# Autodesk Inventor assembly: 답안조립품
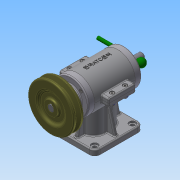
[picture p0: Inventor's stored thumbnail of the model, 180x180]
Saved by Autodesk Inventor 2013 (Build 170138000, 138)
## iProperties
Created: 2015-12
Part Number: 답안조립품
Document SubType Name: Assembly
Designer: Administrator
Author: Administrator
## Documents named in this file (19)
- C:\Users\Administrator\Desktop\351208V1024\답안조립품.iam
- C:\Users\Administrator\Desktop\351208V1024\본체.ipt
- C:\Users\Administrator\Desktop\351208V1024\V-벨트풀리.ipt
- C:\Users\Administrator\Desktop\351208V1024\너트 M4.ipt
- C:\Users\Administrator\Desktop\351208V1024\뒤커버.ipt
- C:\Users\Administrator\Desktop\351208V1024\레바.ipt
- C:\Users\Administrator\Desktop\351208V1024\멈춤나사 M3x8.ipt
- C:\Users\Administrator\Desktop\351208V1024\베어링 6201.ipt
- C:\Users\Administrator\Desktop\351208V1024\베어링 6202.ipt
- C:\Users\Administrator\Desktop\351208V1024\본체커버.ipt
- C:\Users\Administrator\Desktop\351208V1024\볼트 M3x0.5x8.ipt
- C:\Users\Administrator\Desktop\351208V1024\볼트 M4 x 16.ipt
- C:\Users\Administrator\Desktop\351208V1024\스프링.ipt
- C:\Users\Administrator\Desktop\351208V1024\슬라이드.ipt
- C:\Users\Administrator\Desktop\351208V1024\앞커버.ipt
- C:\Users\Administrator\Desktop\351208V1024\오일실 12 22 7.ipt
- C:\Users\Administrator\Desktop\351208V1024\와셔 ST 4-100.ipt
- C:\Users\Administrator\Desktop\351208V1024\키 4 x 4 x 18.ipt
- C:\Users\Administrator\Desktop\351208V1024\편심축.ipt
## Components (13 placed, 4 different names)
1. V-벨트풀리:1 — 플러쉬:1
2. ISO 4032 M4:1
3. ISO 4762 M4 x 16:1
4. ISO 7091 ST 4 - 100 HV:1
5. ISO 4762 M4 x 16:2
6. ISO 4762 M4 x 16:3
7. ISO 4762 M4 x 16:4
8. ISO 7091 ST 4 - 100 HV:2
9. ISO 7091 ST 4 - 100 HV:3
10. ISO 7091 ST 4 - 100 HV:4
11. ISO 4032 M4:2
12. ISO 4032 M4:3
13. ISO 4032 M4:4
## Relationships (1: Flush 1)
- 플러쉬:1 [Flush]: V-벨트풀리:1
